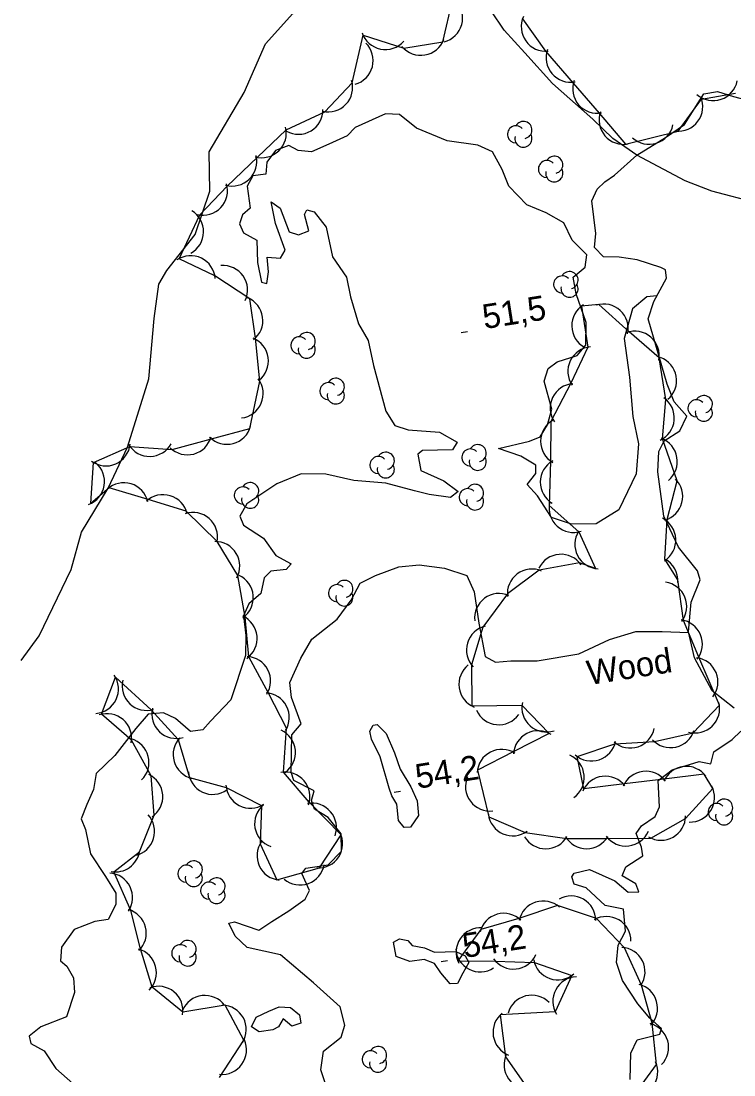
# Model space of a CAD drawing. Extents: x 646142 to 649934, y 5874075 to 5876351.
# Drawn here: x 647630.1 to 647717.4, y 5875611.2 to 5875740.3 of the extents above; entities that cross this region are included whole.
import ezdxf

# ---------------------------------------------------------------- set-up
doc = ezdxf.new("R2010")
doc.units = 0
for name, color, linetype in [('Niveau 1', 7, 'Continuous'), ('Niveau 2', 7, 'Continuous'), ('Niveau 22', 7, 'Continuous'), ('Niveau 3', 7, 'Continuous'), ('Niveau 44', 7, 'Continuous'), ('Niveau 54', 7, 'Continuous')]:
    doc.layers.add(name, color=color, linetype=linetype)

msp = doc.modelspace()

# ---------------------------------------------------------------- linework, layer by layer
at = {"layer": 'Niveau 1'}
for points in [[(647707.96, 5875706.61), (647706.73, 5875706.48), (647704.95, 5875705), (647703.93, 5875701.39), (647704.6, 5875696.65), (647704.99, 5875691.83), (647705.7, 5875688.46), (647705.42, 5875684.81), (647703.3, 5875680.41), (647700.53, 5875678.66), (647697.49, 5875678.63), (647695.04, 5875679.45), (647693.33, 5875682.1), (647692.07, 5875683.5), (647693.13, 5875684.85), (647693.14, 5875685.87), (647691.29, 5875686.98), (647688.56, 5875687.89), (647692.36, 5875688.79), (647693.67, 5875689.32), (647694.54, 5875690.82), (647695.1, 5875692.74), (647694.16, 5875696.15), (647694.63, 5875697.72), (647695.74, 5875698.52), (647698.21, 5875699.28), (647699.27, 5875700.57), (647699.3, 5875703.35), (647698.07, 5875706.84), (647697.71, 5875708.9), (647699.17, 5875710.12), (647699.37, 5875711.61), (647697.57, 5875713.41), (647696.57, 5875715.57), (647694.38, 5875716.76), (647692.03, 5875717.76), (647689.84, 5875720.03), (647689.03, 5875722.09), (647687.81, 5875724.23), (647686.04, 5875725.07), (647682.27, 5875725.59), (647678.51, 5875727.13), (647676.43, 5875728.84), (647674.73, 5875728.89), (647671, 5875727.21), (647670.02, 5875726.2), (647667.8, 5875725.19), (647665.69, 5875724.23), (647664.03, 5875724.4), (647662.9, 5875725.02), (647661.27, 5875724.4), (647660.21, 5875723), (647660.07, 5875721.51), (647658.51, 5875721.29), (647657.78, 5875720.03), (647658.15, 5875717.35), (647657.21, 5875716.52), (647656.86, 5875715.41), (647657.36, 5875714.33), (647658.97, 5875713.42), (647659.05, 5875710.71), (647659.56, 5875708.27), (647660.2, 5875708.11), (647660.4, 5875709.55), (647660.24, 5875711.34)], [(647660.24, 5875711.34), (647661.88, 5875711.23), (647662.47, 5875712.19), (647661.26, 5875715.46), (647660.73, 5875718.12), (647661.82, 5875717.33), (647662.94, 5875714.45), (647664.1, 5875714.06), (647665.35, 5875714.58), (647664.83, 5875716.56), (647665.11, 5875717.16), (647665.98, 5875716.91), (647667.45, 5875715.02), (647668.25, 5875711.37), (647669.95, 5875708.88), (647670.45, 5875706.5), (647671.44, 5875703.16), (647672.59, 5875701.12), (647673.27, 5875698.08), (647674.76, 5875692.47), (647675.88, 5875690.72), (647677.51, 5875690.21), (647681.32, 5875689.92), (647683.52, 5875688.67), (647682.93, 5875687.76), (647679.27, 5875687.67), (647678.69, 5875687.22), (647679.05, 5875685.22), (647681.88, 5875683.93), (647683.63, 5875682.64), (647682.68, 5875681.92), (647680.06, 5875682.27), (647678.27, 5875682.71), (647678.27, 5875682.71), (647674.79, 5875683.65), (647670.87, 5875683.99), (647667.41, 5875684.76), (647664.42, 5875684.79), (647661.43, 5875683.58), (647657.77, 5875681.12), (647656.89, 5875679.61), (647657.33, 5875678.53), (647659.8, 5875676.92), (647661.3, 5875674.81), (647663.2, 5875673.76), (647662.59, 5875673.08), (647660.69, 5875672.88), (647659.86, 5875672.06), (647659.48, 5875670.16), (647658.02, 5875668.88), (647657.37, 5875667.4), (647657.65, 5875665), (647657.59, 5875662.56), (647655.79, 5875657.12), (647653.33, 5875654.5), (647652.36, 5875653.44), (647650.86, 5875653.23), (647649.01, 5875654.85), (647647.54, 5875655.54), (647645.69, 5875655.35), (647644.16, 5875653.61), (647641.6, 5875650.3), (647639.32, 5875648.09), (647639, 5875646.14), (647638.16, 5875644.3)], [(647638.16, 5875644.3), (647637.48, 5875642.53), (647638, 5875641.23), (647638.62, 5875638.25), (647640.45, 5875635.5), (647641.72, 5875633.43), (647641.74, 5875632.07), (647640.78, 5875630.22), (647639.17, 5875629.95), (647636.61, 5875629), (647635.07, 5875626.81), (647634.94, 5875625.16), (647635.74, 5875624.51), (647636.55, 5875623.07), (647636.66, 5875621.28), (647635.7, 5875618.3), (647632.55, 5875617.07), (647631.13, 5875615.91), (647631.33, 5875615.03), (647632.94, 5875614.12), (647634.38, 5875611.95), (647636.47, 5875610.14)]]:
    msp.add_lwpolyline(points, dxfattribs=at)
at = {"layer": 'Niveau 2'}
for points in [[(647630.13, 5875661.92), (647632.33, 5875664.95), (647636.25, 5875673.1), (647637.52, 5875677.65), (647640.8, 5875683.03), (647643.15, 5875688.08), (647645.76, 5875696.45), (647646.42, 5875703.82), (647646.98, 5875708.02), (647647.96, 5875709.7), (647651.44, 5875714.14), (647653.21, 5875719.42), (647653.15, 5875724.23), (647657.44, 5875731.53), (647660.05, 5875737.47), (647663.38, 5875741.21), (647667.66, 5875743.75), (647672.55, 5875748.33)], [(647662.88, 5875631.27), (647664.89, 5875632.71), (647665.41, 5875633.78), (647664.48, 5875635.83), (647664.98, 5875636.5), (647667.7, 5875636.89), (647669.35, 5875638.58), (647669.32, 5875640.72), (647667.72, 5875642.7), (647666.05, 5875643.71), (647665.67, 5875644.8), (647666.01, 5875645.96), (647663.52, 5875647.23), (647663.2, 5875648.27), (647663.28, 5875652.84), (647664.39, 5875654.2), (647663.24, 5875657.41), (647663.02, 5875659.25), (647664.37, 5875662.21), (647665.73, 5875664.55), (647668.82, 5875667.01), (647670.52, 5875669.32), (647671.62, 5875671.41), (647673.5, 5875672.34), (647676.38, 5875673.42), (647678.84, 5875673.67), (647681.97, 5875673.26), (647684.7, 5875672.36), (647685.57, 5875670.36), (647686.15, 5875666.53), (647686.93, 5875662.43), (647688.18, 5875661.72), (647690.07, 5875661.91), (647693.28, 5875661.9), (647698.38, 5875662.76), (647702.16, 5875664.5), (647705.38, 5875665.51), (647708.59, 5875665.5), (647711.82, 5875665.38)], [(647675.16, 5875646.32), (647674.07, 5875650.14), (647673.03, 5875652.32), (647672.82, 5875653.28), (647673.23, 5875654.03), (647673.73, 5875654.08), (647674.82, 5875652.98), (647675.83, 5875650.63), (647676.52, 5875648.62), (647677.85, 5875646.45), (647678.6, 5875644.75), (647678.79, 5875642.97), (647677.78, 5875641.52), (647677.02, 5875641.5), (647676.32, 5875642.35), (647676.1, 5875644.36), (647675.5, 5875645.37), (647675.16, 5875646.32)], [(647704.68, 5875610.63), (647704.77, 5875613.84), (647705.52, 5875615.49), (647708.32, 5875616.17), (647708.53, 5875616.87), (647708.53, 5875616.87), (647707.07, 5875618.13), (647705.61, 5875619.89), (647703.72, 5875622.73), (647703.01, 5875624.96), (647703.2, 5875627.06), (647704.11, 5875628.79), (647703.86, 5875631.46), (647701.63, 5875631.91), (647699.29, 5875634.08), (647697.84, 5875634.55), (647697.54, 5875635.42), (647697.83, 5875635.9), (647699.7, 5875636.32), (647702.8, 5875634.95), (647704.45, 5875633.55), (647705.74, 5875633.62), (647705.36, 5875634.6), (647703.7, 5875635.55), (647704.16, 5875636.67), (647706.23, 5875638), (647706.07, 5875639.06), (647705.41, 5875640.73), (647706.05, 5875641.7), (647707.74, 5875642.83), (647708.25, 5875644.01), (647708.12, 5875647.26), (647709.83, 5875648.54), (647713.11, 5875649.55), (647714.54, 5875649.3), (647714.91, 5875650.75), (647717.18, 5875652.27)], [(647717.18, 5875652.27), (647718.21, 5875653.28)], [(647667.5, 5875609.71), (647666.8, 5875611.78), (647666.8, 5875611.78), (647667.14, 5875614.07), (647669.29, 5875615.81), (647669.77, 5875617.27), (647669.17, 5875619.52), (647665.91, 5875622.45), (647661.87, 5875625.87), (647657.79, 5875626.8), (647656.31, 5875628.17), (647655.54, 5875629.78), (647656.26, 5875629.91), (647659.22, 5875628.92), (647660.81, 5875629.98), (647662.88, 5875631.27)], [(647678.01, 5875627.03), (647679.5, 5875626.73), (647680.73, 5875626.21), (647683.36, 5875626.31), (647684.5, 5875625.78), (647684.92, 5875624.95), (647684.2, 5875623.64), (647683.56, 5875622.37), (647682.66, 5875622.33), (647681.5, 5875623.7), (647680.74, 5875624.83), (647679.46, 5875625.32), (647677.72, 5875625.06), (647676.05, 5875625.7), (647675.7, 5875627.44), (647676.44, 5875627.85), (647677.47, 5875627.65), (647678.01, 5875627.03)], [(647660.93, 5875616.69), (647659.27, 5875616.47), (647658.34, 5875617.05), (647658.9, 5875618.23), (647660.44, 5875618.98), (647661.71, 5875619.51), (647663.12, 5875619.45), (647664.22, 5875618.53), (647664.37, 5875617.53), (647663.26, 5875617.13), (647662.19, 5875618.03), (647661.63, 5875617.05), (647660.93, 5875616.69)]]:
    msp.add_lwpolyline(points, dxfattribs=at)
at = {"layer": 'Niveau 22'}
msp.add_lwpolyline([(647748.06, 5875704.18), (647741.83, 5875709.31), (647733, 5875713.27), (647725.63, 5875716.03), (647720.25, 5875717.97), (647714.69, 5875719.44), (647711.41, 5875720.69), (647705.48, 5875723.82), (647702.57, 5875725.9), (647700.09, 5875728.26), (647695.16, 5875732.62), (647691.77, 5875736.36), (647689.24, 5875739.16), (647686.08, 5875743.94), (647684.38, 5875747.62), (647683.97, 5875750.86), (647684.27, 5875757.25)], dxfattribs=at)
at = {"layer": 'Niveau 3'}
for p, q in [((647683.98, 5875702.13), (647684.77, 5875702.25)), ((647675.78, 5875645.81), (647676.57, 5875645.93)), ((647681.54, 5875625.08), (647682.33, 5875625.2))]:
    msp.add_line(p, q, dxfattribs=at)
at = {"layer": 'Niveau 44'}
for points in [[(647657.54, 5875667.23), (647656.65, 5875672.35), (647654.14, 5875676.5), (647650.34, 5875680.23), (647645.7, 5875681.64), (647640.92, 5875683.1), (647638.68, 5875681.17), (647638.99, 5875686.18), (647643.44, 5875688.14), (647648.6, 5875687.8), (647653.29, 5875689.06), (647658.12, 5875690.35), (647659.34, 5875696.17), (647658.8, 5875701.43), (647658.13, 5875706.23), (647653.84, 5875709.05), (647649.47, 5875711.16), (647651.99, 5875716.52), (647655.34, 5875720.04), (647659.06, 5875723.58), (647662.56, 5875726.94), (647667.32, 5875729.15), (647670.65, 5875732.68), (647671.98, 5875738.54), (647676.96, 5875736.93), (647681.75, 5875737.74), (647682.94, 5875742.78)], [(647691.5, 5875740.52), (647694.32, 5875736.57), (647697.72, 5875732.67), (647700.87, 5875728.98), (647704.11, 5875725.17), (647710.54, 5875726.77), (647713.42, 5875730.68), (647717.57, 5875731.43)], [(647698.49, 5875673.89), (647693.54, 5875673.01), (647689.65, 5875670.1), (647686.64, 5875666.04), (647685.26, 5875661.39), (647685.3, 5875656.37), (647691.43, 5875656.48), (647694.75, 5875653.01), (647690.43, 5875650.8), (647685.98, 5875648.52), (647687.37, 5875642.8), (647691.83, 5875640.87), (647696.92, 5875640.12), (647701.78, 5875640.14), (647707.21, 5875640.19), (647711.44, 5875642.58), (647714.78, 5875646.28), (647713.75, 5875648.02), (647708.79, 5875647.42), (647703.97, 5875646.83), (647699.01, 5875646.23), (647698.21, 5875650.19), (647702.81, 5875651.73), (647707.64, 5875652.01), (647712.38, 5875653.06), (647715.6, 5875656.48), (647713.07, 5875662.36), (647711.22, 5875666.84), (647710.52, 5875671.83), (647708.91, 5875674.35), (647709.2, 5875679.23), (647710.42, 5875683.93), (647708.62, 5875689.08), (647709.06, 5875693.91), (647708.23, 5875699.03), (647704.55, 5875702.2), (647700.84, 5875705.54), (647698.72, 5875705.34), (647699.51, 5875700.31), (647697.41, 5875695.93), (647694.98, 5875691.22), (647694.93, 5875686.37), (647694.76, 5875680.93), (647698.38, 5875677.7), (647700.45, 5875673.2), (647698.49, 5875673.89)], [(647654.42, 5875610.88), (647657.4, 5875615.43), (647655.09, 5875619.7), (647649.94, 5875618.86), (647646.19, 5875621.94), (647644.76, 5875626.63), (647643.55, 5875631.33), (647641.46, 5875636.05), (647644.63, 5875638.52), (647646.41, 5875642.99), (647646.04, 5875647.83), (647643.64, 5875652.17), (647639.97, 5875655.35), (647641.68, 5875659.89), (647646.04, 5875655.88), (647649.36, 5875652.25), (647650.73, 5875647.59), (647655.24, 5875646.37), (647659.56, 5875644.16), (647659.38, 5875639.49), (647661.42, 5875635.08), (647666.65, 5875636.53), (647669.29, 5875640.6), (647665.4, 5875644.57), (647662.25, 5875648.26), (647662.63, 5875653.63), (647660.41, 5875657.95), (647658, 5875662.4), (647657.54, 5875667.23)], [(647705.06, 5875608.53), (647707.9, 5875612.47), (647707.39, 5875617.5), (647706.08, 5875622.18), (647703.99, 5875626.76), (647700.57, 5875630.33), (647695.8, 5875631.91), (647691.06, 5875630.32), (647686.39, 5875629), (647683.57, 5875625.15), (647688.17, 5875625.13), (647692.95, 5875624.96), (647697.53, 5875623.35), (647695.51, 5875618.89), (647688.77, 5875618.53), (647689.4, 5875613.4), (647692.2, 5875609.44)]]:
    msp.add_lwpolyline(points, dxfattribs=at)
for centre, radius, start, end in [((647681.17, 5875740.64), 3, 284.3056, 44.2835), ((647694.35, 5875739.57), 3, 155.6029, 275.5809), ((647674.71, 5875739.78), 3, 198.4951, 318.4731), ((647670.22, 5875735.43), 3, 285.1429, 45.1209), ((647679.06, 5875739.07), 3, 219.55, 339.528), ((647697.39, 5875735.77), 3, 160.4552, 280.4331), ((647667.71, 5875732.13), 3, 256.6699, 16.6479), ((647700.64, 5875731.97), 3, 160.4552, 280.4331), ((647714.84, 5875733.53), 3, 228.6579, 348.6359), ((647710.56, 5875729.77), 3, 263.6408, 23.6187), ((647664.08, 5875729.4), 3, 240.8232, 0.8011), ((647703.88, 5875728.16), 3, 160.4552, 280.4331), ((647659.59, 5875726.53), 3, 253.916, 13.8939), ((647690.71, 5875726.39), 1.05, 44.1154, 269.804), ((647691.61, 5875726.92), 1.05, 282.2692, 149.7263), ((647706.98, 5875728.17), 3, 227.8672, 347.8451), ((647691.61, 5875725.87), 1.05, 166.9369, 29.6212), ((647655.98, 5875723.06), 3, 253.916, 13.8939), ((647694.49, 5875722.14), 1.05, 44.1154, 269.804), ((647695.39, 5875722.67), 1.05, 282.2692, 149.7263), ((647695.39, 5875721.62), 1.05, 166.9369, 29.6212), ((647652.39, 5875719.49), 3, 256.4328, 16.4107), ((647649.47, 5875714.48), 3, 298.5652, 58.5431), ((647650.89, 5875708.52), 3, 4.267, 124.245), ((647654.85, 5875707.32), 3, 335.0061, 94.984), ((647696.36, 5875708), 1.05, 44.1154, 269.804), ((647697.26, 5875708.53), 1.05, 282.2692, 149.7263), ((647697.26, 5875707.48), 1.05, 166.9369, 29.6212), ((647656.72, 5875703.59), 3, 307.9097, 67.8877), ((647700.53, 5875702.94), 3, 121.0738, 241.0518), ((647701.43, 5875702.6), 3, 347.3535, 107.3314), ((647657.4, 5875698.63), 3, 307.9097, 67.8877), ((647664.19, 5875700.54), 1.05, 44.1154, 269.804), ((647665.09, 5875701.07), 1.05, 282.2692, 149.7263), ((647705.24, 5875699.28), 3, 349.2788, 109.2567), ((647665.09, 5875700.02), 1.05, 166.9369, 29.6212), ((647700.05, 5875697.36), 3, 94.4406, 214.4186), ((647707.36, 5875696.23), 3, 310.1057, 70.0837), ((647656.76, 5875694.63), 3, 276.7597, 36.7377), ((647668.65, 5875695.46), 1.05, 282.2692, 149.7263), ((647667.75, 5875694.93), 1.05, 44.1154, 269.804), ((647668.65, 5875694.41), 1.05, 166.9369, 29.6212), ((647697.89, 5875692.85), 3, 94.4406, 214.4186), ((647707.08, 5875691.65), 3, 294.89, 54.8679), ((647712.8, 5875692.82), 1.05, 44.1154, 269.804), ((647713.7, 5875693.35), 1.05, 282.2692, 149.7263), ((647713.7, 5875692.3), 1.05, 166.9369, 29.6212), ((647696.72, 5875688.78), 3, 119.4615, 239.4394), ((647655.32, 5875691.42), 3, 224.9954, 344.9733), ((647640.5, 5875688.77), 3, 233.8092, 353.7871), ((647645.87, 5875689.94), 3, 211.2497, 331.2276), ((647650.49, 5875690.13), 3, 224.9954, 344.9733), ((647686.02, 5875687.33), 1.05, 282.2692, 149.7263), ((647707.45, 5875686.32), 3, 309.5486, 69.5266), ((647674.77, 5875686.41), 1.05, 282.2692, 149.7263), ((647685.12, 5875686.8), 1.05, 44.1154, 269.804), ((647637.34, 5875683.86), 3, 290.5168, 50.4947), ((647673.87, 5875685.88), 1.05, 44.1154, 269.804), ((647674.77, 5875685.36), 1.05, 166.9369, 29.6212), ((647686.02, 5875686.28), 1.05, 166.9369, 29.6212), ((647696.67, 5875683.78), 3, 119.4615, 239.4394), ((647642.72, 5875680.71), 3, 13.0514, 133.0294), ((647657.27, 5875682.15), 1.05, 44.1154, 269.804), ((647658.17, 5875682.68), 1.05, 282.2692, 149.7263), ((647685.69, 5875682.47), 1.05, 282.2692, 149.7263), ((647708.11, 5875682.03), 3, 285.4489, 45.4268), ((647647.51, 5875679.25), 3, 13.0514, 133.0294), ((647658.17, 5875681.63), 1.05, 166.9369, 29.6212), ((647684.79, 5875681.94), 1.05, 44.1154, 269.804), ((647685.69, 5875681.42), 1.05, 166.9369, 29.6212), ((647697.74, 5875680.63), 3, 168.2687, 288.2467), ((647651.17, 5875677.08), 3, 348.615, 108.5929), ((647707.26, 5875676.68), 3, 303.0465, 63.0244), ((647700.9, 5875676.17), 3, 147.5138, 267.4918), ((647653.89, 5875673.51), 3, 331.1363, 91.1142), ((647696.21, 5875671.95), 3, 34.4039, 154.3818), ((647707.53, 5875671.69), 3, 356.5847, 63.0244), ((647692.65, 5875670.14), 3, 66.7292, 186.7072), ((647655.55, 5875669.63), 3, 305.3924, 65.3704), ((647669.7, 5875670.71), 1.05, 282.2692, 149.7263), ((647668.8, 5875670.18), 1.05, 44.1154, 269.804), ((647708.61, 5875668.55), 3, 322.4401, 82.4181), ((647669.7, 5875669.66), 1.05, 166.9369, 29.6212), ((647688.64, 5875667.15), 3, 66.7292, 186.7072), ((647656.02, 5875664.65), 3, 305.3924, 65.3704), ((647710.52, 5875663.93), 3, 322.4401, 82.4181), ((647687.64, 5875663.22), 3, 103.5179, 223.4959), ((647657.67, 5875659.43), 3, 327.2342, 87.2121), ((647686.71, 5875659.02), 3, 127.8549, 247.8329), ((647712.42, 5875659.31), 3, 322.4401, 82.4181), ((647639.05, 5875658.45), 3, 274.5807, 34.5586), ((647645.49, 5875658.83), 3, 166.6236, 286.6016), ((647659.96, 5875654.98), 3, 327.2342, 87.2121), ((647649.12, 5875655.4), 3, 166.6236, 286.6016), ((647694.42, 5875656.18), 3, 168.2856, 288.2636), ((647712.63, 5875656.06), 3, 254.1536, 14.1316), ((647640.65, 5875652.43), 3, 349.0214, 108.9994), ((647688.6, 5875657.07), 3, 204.2918, 324.2698), ((647704.69, 5875654.22), 3, 228.5202, 348.4981), ((647642.78, 5875649.45), 3, 314.3263, 74.3042), ((647651.74, 5875650.42), 3, 136.4778, 256.4558), ((647660.71, 5875650.68), 3, 305.3886, 65.3665), ((647693.4, 5875650.34), 3, 57.126, 177.1039), ((647709.63, 5875654.26), 3, 222.4519, 342.4298), ((647688.95, 5875648.06), 3, 57.126, 177.1039), ((647699.95, 5875652.63), 3, 228.5202, 348.4981), ((647696.06, 5875647.6), 3, 305.3574, 65.3354), ((647706.59, 5875645.37), 3, 36.937, 156.9149), ((647711.56, 5875645.97), 3, 36.937, 156.9149), ((647644.47, 5875645.27), 3, 304.2986, 64.2766), ((647653.59, 5875648.54), 3, 184.9423, 304.9202), ((647662.48, 5875645.27), 3, 340.5264, 100.5043), ((647687.52, 5875646.5), 3, 156.9199, 276.8978), ((647701.63, 5875644.77), 3, 36.937, 156.9149), ((647658.2, 5875646.84), 3, 182.9915, 302.9694), ((647712.01, 5875645.15), 3, 268.161, 28.1389), ((647665.73, 5875641.47), 3, 340.5264, 100.5043), ((647716.18, 5875643.91), 1.05, 282.2692, 149.7263), ((647661.71, 5875641.96), 3, 129.9369, 249.9149), ((647715.28, 5875643.38), 1.05, 44.1154, 269.804), ((647716.18, 5875642.86), 1.05, 166.9369, 29.6212), ((647643.47, 5875641), 3, 282.9592, 42.9372), ((647690.3, 5875643.46), 3, 186.58, 306.558), ((647708.46, 5875642.92), 3, 239.5183, 359.4962), ((647666.49, 5875639.52), 3, 267.121, 27.099), ((647704.15, 5875642.21), 3, 216.8117, 336.7897), ((647662, 5875638.03), 3, 144.8757, 264.8536), ((647694.34, 5875641.87), 3, 210.2474, 330.2253), ((647699.34, 5875641.89), 3, 210.2474, 330.2253), ((647641.67, 5875639.04), 3, 259.9517, 351.1652), ((647650.37, 5875635.82), 1.05, 44.1154, 269.804), ((647651.27, 5875636.35), 1.05, 282.2692, 149.7263), ((647664.27, 5875637.44), 3, 229.8994, 349.8774), ((647640.77, 5875632.91), 3, 326.0185, 85.9965), ((647651.27, 5875635.3), 1.05, 166.9369, 29.6212), ((647653.15, 5875633.74), 1.05, 44.1154, 269.804), ((647654.05, 5875634.27), 1.05, 282.2692, 149.7263), ((647654.05, 5875633.22), 1.05, 166.9369, 29.6212), ((647697.46, 5875630.1), 3, 359.8121, 119.79), ((647694.03, 5875629.48), 3, 48.0275, 168.0054), ((647642.45, 5875628.54), 3, 314.4185, 74.3964), ((647689.21, 5875627.97), 3, 45.7832, 165.7611), ((647701.78, 5875627.58), 3, 359.8121, 119.79), ((647686.38, 5875626.2), 3, 86.5572, 206.5351), ((647643.69, 5875623.7), 3, 314.4185, 74.3964), ((647649.61, 5875626.08), 1.05, 44.1154, 269.804), ((647650.51, 5875626.61), 1.05, 282.2692, 149.7263), ((647686.32, 5875626.79), 3, 182.9952, 302.9731), ((647703.5, 5875623.8), 3, 326.6689, 86.6468), ((647650.51, 5875625.56), 1.05, 166.9369, 29.6212), ((647690.4, 5875627.14), 3, 215.8927, 335.8706), ((647695.82, 5875625.82), 3, 190.706, 310.6839), ((647698.21, 5875620.2), 3, 91.844, 211.822), ((647646.94, 5875619.03), 3, 350.6439, 110.6219), ((647705.03, 5875619.36), 3, 315.6702, 75.6481), ((647652.64, 5875617.91), 3, 37.0839, 157.0619), ((647692.63, 5875617.94), 3, 44.5584, 164.5363), ((647654.69, 5875616.73), 3, 328.3584, 88.3363), ((647690.89, 5875616.4), 3, 128.8354, 248.8134), ((647706.38, 5875614.55), 3, 315.6702, 75.6481), ((647654.72, 5875614.24), 3, 264.266, 24.244), ((647672.92, 5875613.08), 1.05, 44.1154, 269.804), ((647673.82, 5875613.61), 1.05, 282.2692, 149.7263), ((647692.24, 5875612.44), 3, 155.2376, 275.2155), ((647673.82, 5875612.56), 1.05, 166.9369, 29.6212), ((647705.05, 5875611.53), 3, 264.2507, 24.2286)]:
    msp.add_arc(centre, radius, start, end, dxfattribs=at)
at = {"layer": 'Niveau 54'}
for points in [[(647709.2, 5875695.79), (647706.88, 5875703.8), (647707.58, 5875705.91), (647709.12, 5875708.78), (647709.02, 5875709.78), (647708.43, 5875710.06), (647705.52, 5875711.01), (647703.35, 5875711.35), (647701.43, 5875711.38), (647700.3, 5875712.51), (647700.48, 5875714.23), (647700, 5875718.25), (647700.65, 5875719.68), (647701.59, 5875720.57), (647702.75, 5875721.37), (647705.48, 5875723.82), (647709, 5875725.99), (647711.34, 5875727.59), (647713.7, 5875731.34), (647715.37, 5875731.63), (647717.34, 5875731.04), (647721.97, 5875729.81)], [(647717.4, 5875656.12), (647714.73, 5875658.21), (647712.55, 5875662.27), (647711.8, 5875665.46), (647712.14, 5875669.1), (647713.24, 5875671.81), (647712.91, 5875672.91), (647710.61, 5875675.83), (647708.8, 5875679.6), (647708.06, 5875685.05), (647708.17, 5875687.55), (647708.83, 5875688.86), (647710.75, 5875690.07), (647711.6, 5875691.85), (647710.08, 5875693.62), (647709.2, 5875695.79)]]:
    msp.add_lwpolyline(points, dxfattribs=at)

# ---------------------------------------------------------------- texts
at = {"layer": 'Niveau 3'}
for s, p in [('51,5 ', (647686.84, 5875702.53)), ('54,2 ', (647678.63, 5875646.22)), ('54,2 ', (647684.4, 5875625.49))]:
    msp.add_text(s, height=3, rotation=8.9405, dxfattribs=at).set_placement(p)
at = {"layer": 'Niveau 44'}
msp.add_text('Wood', height=3, rotation=8.9405, dxfattribs=at).set_placement((647699.63, 5875658.92))

doc.saveas('drawing.dxf')
